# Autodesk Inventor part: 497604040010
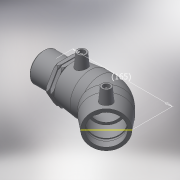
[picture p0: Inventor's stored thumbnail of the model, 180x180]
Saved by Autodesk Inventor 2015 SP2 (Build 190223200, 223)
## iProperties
Created: 2017-06
Part Number: 497604040010
Material: Generic
Description: PLASSON PE MALE TRANSITION 45° ELBOW 40-1"
Document SubType Name: Modeling
Designer: KIM
Mass: 55.0731 g
Surface Area: 148.067 cm^2
Volume: 55.0731 cm^3
Density: 1 g/cm^3
Appearance: Default
Author: KIM
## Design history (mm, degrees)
derived "497604.ipt"
feature "Solid1::497604.ipt"
tag "TaggingFeature1"
body "Solid1"
other parameters: "d2" = 56, "d4" = 25.75, "d5" = 50.4, "d8" = 168 deg, "d10" = 16.8, "d11" = 5.6, "d29" = 47, "d30" = 15, "d31" = 36.05, "d34" = 5 deg, "d41" = 4, "d42" = 14, "d43" = 0, "d50" = 34, "d51" = 16.8, "d52" = 41.9, "d54" = 135 deg, "d86" = 25.2, "d87" = 135 deg, "d88" = 103, "d90" = 33.6, "d91" = 0, "d92" = 42, "d93" = 0, "d101" = 3, "d102" = 0, "d107" = 0.1, "d109" = 33.249, "d110" = 42, "d111" = 10.5, "d112" = 56, "d113" = 23.2743, "d114" = 37.8, "d116" = 1.68, "d122" = 0, "d123" = 1.66245, "d126" = 1.05, "d127" = 4.725, "d128" = 56, "d130" = 42, "L_" = 145, "L_2" = 42, "A_" = 47, "d_2" = 12, "L_1" = 42, "R_" = 33.249, "D_1" = 56, "d129" = 145
